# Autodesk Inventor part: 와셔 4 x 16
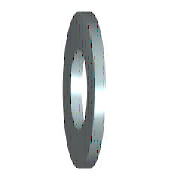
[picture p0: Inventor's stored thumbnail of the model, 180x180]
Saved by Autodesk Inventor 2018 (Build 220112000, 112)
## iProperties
IsCustomPart: 1
Created: 2012-02
Part Number: 와셔 4 x 16
Material: 강철, 연강
Description: 미터법 평면 와셔
Document SubType Name: Modeling
Standard: ANSI B18.22M
Designer: mduedu
Standard Revision: 1999
Standards Organization: ANSI
Language: ko-KR
Size Designation: 4 W
Categories: <MemberInstance><Categories><Category DisplayName="조임쇠" InternalName="e4da775c-781d-43d5-af7c-5136215cf5a6" Mnemonic="FSTN"><Category DisplayName="와셔" InternalN
Density: 1 g/cm^3
Appearance: 파란색 - 벽 페인트 - 광택
Author: mduedu
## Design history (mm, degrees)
sketch "스케치"
  geometry: C1 r 8 at (0, 0); C2 r 2.35 at (0, 0); 1 further point
  constraints: 2 centre point, 2 coincident
  dimensions: "d0" = 4.7 diameter of C2 (= SD1); "d1" = 16 diameter of C1 (= SD2)
extrude "본체" new body sketch "스케치" distance "d2" = 2.3 (= SD); taper "d3" = 0 deg
workaxis "Work Axis1"
workplane "Work Plane1"
body "Solid1"
other parameters: "SD1" = 4.7 [user parameter; used in 1 equation term], "SD2" = 16 [user parameter; used in 1 equation term], "SD" = 2.3 [user parameter; used in 1 equation term], "d4" = 0, "d5" = 0, "d6" = 0, "d7" = 0, "NND" = 4 [user parameter]
